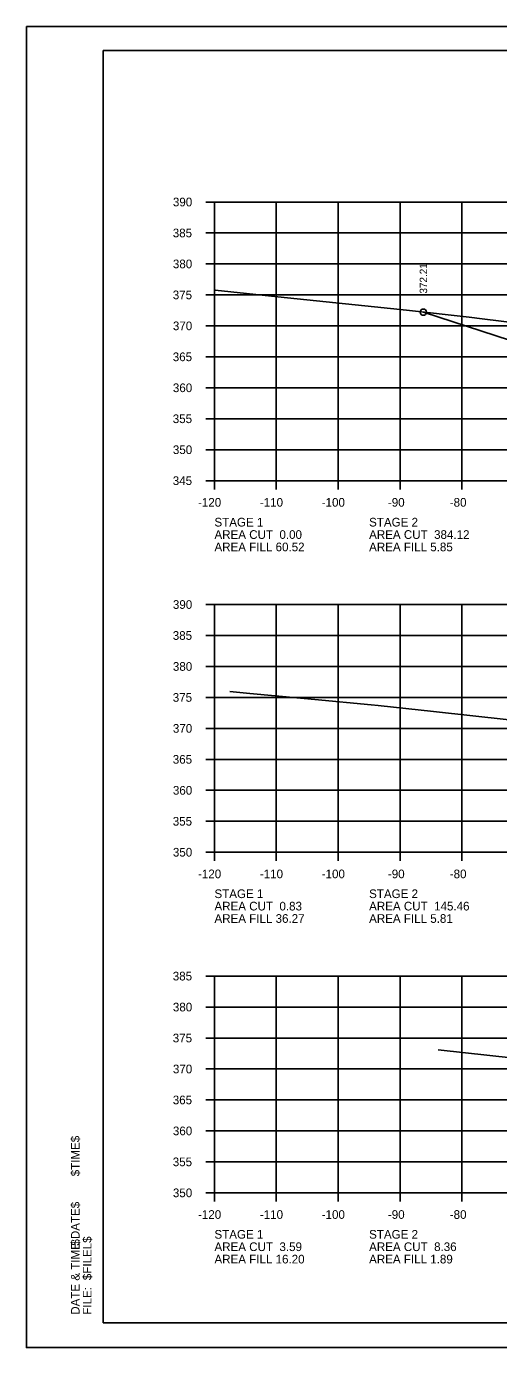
# Model space of a CAD drawing. Extents: x 1630712 to 1632516, y 782146 to 785403.
# Drawn here: x 1632182.6 to 1632258.9, y 783696.6 to 783910 of the extents above; entities that cross this region are included whole.
import ezdxf

# ---------------------------------------------------------------- set-up
doc = ezdxf.new("R2010")
doc.units = 0
for name, color, linetype in [('Default', 7, 'Continuous'), ('R_Axis', 7, 'Continuous'), ('R_Axis Annot', 7, 'Continuous'), ('R_Border', 7, 'Continuous'), ('R_Exist Surface', 7, 'Continuous'), ('R_Fin Surface', 7, 'Continuous'), ('R_Grid', 7, 'Continuous'), ('R_No Plot', 7, 'Continuous'), ('R_Xsect Elev', 7, 'Continuous')]:
    doc.layers.add(name, color=color, linetype=linetype)

msp = doc.modelspace()

# ---------------------------------------------------------------- linework, layer by layer
at = {"layer": 'R_Axis'}
for p, q in [((1632211.56, 783881.62), (1632212.96, 783881.62)), ((1632212.96, 783836.62), (1632212.96, 783881.62)), ((1632211.56, 783876.62), (1632212.96, 783876.62)), ((1632211.56, 783871.62), (1632212.96, 783871.62)), ((1632211.56, 783866.62), (1632212.96, 783866.62)), ((1632211.56, 783861.62), (1632212.96, 783861.62)), ((1632211.56, 783856.62), (1632212.96, 783856.62)), ((1632211.56, 783851.62), (1632212.96, 783851.62)), ((1632211.56, 783846.62), (1632212.96, 783846.62)), ((1632211.56, 783841.62), (1632212.96, 783841.62)), ((1632211.56, 783836.62), (1632212.96, 783836.62)), ((1632212.96, 783836.62), (1632492.96, 783836.62)), ((1632212.96, 783835.22), (1632212.96, 783836.62)), ((1632222.96, 783835.22), (1632222.96, 783836.62)), ((1632232.96, 783835.22), (1632232.96, 783836.62)), ((1632242.96, 783835.22), (1632242.96, 783836.62)), ((1632252.96, 783835.22), (1632252.96, 783836.62)), ((1632211.56, 783816.62), (1632212.96, 783816.62)), ((1632212.96, 783776.62), (1632212.96, 783816.62)), ((1632211.56, 783811.62), (1632212.96, 783811.62)), ((1632211.56, 783806.62), (1632212.96, 783806.62)), ((1632211.56, 783801.62), (1632212.96, 783801.62)), ((1632211.56, 783796.62), (1632212.96, 783796.62)), ((1632211.56, 783791.62), (1632212.96, 783791.62)), ((1632211.56, 783786.62), (1632212.96, 783786.62)), ((1632211.56, 783781.62), (1632212.96, 783781.62)), ((1632211.56, 783776.62), (1632212.96, 783776.62)), ((1632212.96, 783776.62), (1632492.96, 783776.62)), ((1632212.96, 783775.22), (1632212.96, 783776.62)), ((1632222.96, 783775.22), (1632222.96, 783776.62)), ((1632232.96, 783775.22), (1632232.96, 783776.62)), ((1632242.96, 783775.22), (1632242.96, 783776.62)), ((1632252.96, 783775.22), (1632252.96, 783776.62)), ((1632211.56, 783756.62), (1632212.96, 783756.62)), ((1632212.96, 783721.62), (1632212.96, 783756.62)), ((1632211.56, 783751.62), (1632212.96, 783751.62)), ((1632211.56, 783746.62), (1632212.96, 783746.62)), ((1632211.56, 783741.62), (1632212.96, 783741.62)), ((1632211.56, 783736.62), (1632212.96, 783736.62)), ((1632211.56, 783731.62), (1632212.96, 783731.62)), ((1632211.56, 783726.62), (1632212.96, 783726.62)), ((1632211.56, 783721.62), (1632212.96, 783721.62)), ((1632212.96, 783721.62), (1632492.96, 783721.62)), ((1632212.96, 783720.22), (1632212.96, 783721.62)), ((1632222.96, 783720.22), (1632222.96, 783721.62)), ((1632232.96, 783720.22), (1632232.96, 783721.62)), ((1632242.96, 783720.22), (1632242.96, 783721.62)), ((1632252.96, 783720.22), (1632252.96, 783721.62))]:
    msp.add_line(p, q, dxfattribs=at)
at = {"layer": 'R_Border'}
for p, q in [((1632194.96, 783906.08), (1632511.14, 783906.08)), ((1632194.96, 783700.62), (1632194.96, 783906.08)), ((1632511.14, 783700.62), (1632194.96, 783700.62))]:
    msp.add_line(p, q, dxfattribs=at)
at = {"layer": 'R_Exist Surface'}
for points in [[(1632212.96, 783867.43), (1632213.1, 783867.41), (1632223.18, 783866.31), (1632238.84, 783864.7), (1632243.99, 783864.13), (1632254.16, 783863.01), (1632256.26, 783862.76), (1632300.13, 783857.36)], [(1632215.45, 783802.57), (1632218.68, 783802.27), (1632226.86, 783801.5), (1632229.21, 783801.28), (1632238.28, 783800.41), (1632239.45, 783800.31), (1632248.39, 783799.37), (1632278.73, 783795.99)], [(1632249.13, 783744.72), (1632273.69, 783742.03), (1632298.1, 783739.36), (1632301.03, 783738.39), (1632313.8, 783733.93), (1632319.57, 783735.36), (1632321.19, 783735.74), (1632322.85, 783736.03), (1632323.29, 783736.12), (1632330.98, 783736.3), (1632332.54, 783736.34), (1632334.1, 783736.31), (1632342.1, 783736.17), (1632342.88, 783736.1), (1632345.78, 783735.86), (1632351.76, 783734.3), (1632353.45, 783733.85), (1632358.72, 783733.99), (1632375.15, 783734.43), (1632381.34, 783733.77), (1632385.36, 783733.3), (1632403.49, 783731.55)]]:
    msp.add_lwpolyline(points, dxfattribs=at)
at = {"layer": 'R_Fin Surface'}
msp.add_lwpolyline([(1632246.74, 783863.83), (1632281.81, 783852.44), (1632296.96, 783847.09), (1632310.79, 783850.54), (1632314.96, 783851.59), (1632320.96, 783851.83), (1632332.96, 783852.07), (1632344.96, 783851.83), (1632350.96, 783851.59), (1632355.14, 783850.54), (1632368.96, 783847.09), (1632368.96, 783847.09), (1632376.31, 783849.54)], dxfattribs=at)
at = {"layer": 'R_Grid'}
for p, q in [((1632212.96, 783881.62), (1632492.96, 783881.62)), ((1632212.96, 783836.62), (1632212.96, 783881.62)), ((1632222.96, 783836.62), (1632222.96, 783881.62)), ((1632232.96, 783836.62), (1632232.96, 783881.62)), ((1632242.96, 783836.62), (1632242.96, 783881.62)), ((1632252.96, 783836.62), (1632252.96, 783881.62)), ((1632212.96, 783876.62), (1632492.96, 783876.62)), ((1632212.96, 783871.62), (1632492.96, 783871.62)), ((1632212.96, 783866.62), (1632492.96, 783866.62)), ((1632212.96, 783861.62), (1632492.96, 783861.62)), ((1632212.96, 783856.62), (1632492.96, 783856.62)), ((1632212.96, 783851.62), (1632492.96, 783851.62)), ((1632212.96, 783846.62), (1632492.96, 783846.62)), ((1632212.96, 783841.62), (1632492.96, 783841.62)), ((1632212.96, 783836.62), (1632492.96, 783836.62)), ((1632212.96, 783816.62), (1632492.96, 783816.62)), ((1632212.96, 783776.62), (1632212.96, 783816.62)), ((1632222.96, 783776.62), (1632222.96, 783816.62)), ((1632232.96, 783776.62), (1632232.96, 783816.62)), ((1632242.96, 783776.62), (1632242.96, 783816.62)), ((1632252.96, 783776.62), (1632252.96, 783816.62)), ((1632212.96, 783811.62), (1632492.96, 783811.62)), ((1632212.96, 783806.62), (1632492.96, 783806.62)), ((1632212.96, 783801.62), (1632492.96, 783801.62)), ((1632212.96, 783796.62), (1632492.96, 783796.62)), ((1632212.96, 783791.62), (1632492.96, 783791.62)), ((1632212.96, 783786.62), (1632492.96, 783786.62)), ((1632212.96, 783781.62), (1632492.96, 783781.62)), ((1632212.96, 783776.62), (1632492.96, 783776.62)), ((1632212.96, 783756.62), (1632492.96, 783756.62)), ((1632212.96, 783721.62), (1632212.96, 783756.62)), ((1632222.96, 783721.62), (1632222.96, 783756.62)), ((1632232.96, 783721.62), (1632232.96, 783756.62)), ((1632242.96, 783721.62), (1632242.96, 783756.62)), ((1632252.96, 783721.62), (1632252.96, 783756.62)), ((1632212.96, 783751.62), (1632492.96, 783751.62)), ((1632212.96, 783746.62), (1632492.96, 783746.62)), ((1632212.96, 783741.62), (1632492.96, 783741.62)), ((1632212.96, 783736.62), (1632492.96, 783736.62)), ((1632212.96, 783731.62), (1632492.96, 783731.62)), ((1632212.96, 783726.62), (1632492.96, 783726.62)), ((1632212.96, 783721.62), (1632492.96, 783721.62))]:
    msp.add_line(p, q, dxfattribs=at)
at = {"layer": 'R_No Plot'}
for p, q in [((1632182.56, 783909.97), (1632515.9, 783909.97)), ((1632182.56, 783696.64), (1632515.9, 783696.64))]:
    msp.add_line(p, q, dxfattribs=at)
msp.add_lwpolyline([(1632182.56, 783909.97), (1632515.9, 783909.97), (1632515.9, 783696.63), (1632182.56, 783696.63)], close=True, dxfattribs=at)
msp.add_circle((1632246.74, 783863.83), 0.5, dxfattribs=at)

# ---------------------------------------------------------------- texts
at = {"layer": 'Default'}
for s, height, p in [('$TIME$', 1.397, (1632191.16, 783724.29)), ('$DATE$', 1.397, (1632191.16, 783713.11)), ('DATE & TIME:', 1.3968, (1632191.16, 783701.94)), ('$FILEL$', 1.397, (1632193.08, 783707.53)), ('FILE: ', 1.397, (1632193.08, 783701.94))]:
    msp.add_text(s, height=height, rotation=90, dxfattribs=at).set_placement(p)
at = {"layer": 'R_Axis'}
for p in [(1632212.96, 783836.62), (1632212.96, 783776.62), (1632212.96, 783721.62)]:
    msp.add_text('-', height=0.0001, dxfattribs=at).set_placement(p)
at = {"layer": 'R_Axis Annot'}
for s, p in [('390', (1632206.24, 783880.92)), ('385', (1632206.22, 783875.92)), ('380', (1632206.24, 783870.92)), ('375', (1632206.22, 783865.92)), ('370', (1632206.24, 783860.92)), ('365', (1632206.22, 783855.92)), ('360', (1632206.24, 783850.92)), ('355', (1632206.22, 783845.92)), ('350', (1632206.24, 783840.92)), ('345', (1632206.22, 783835.92)), ('-120', (1632210.3, 783832.42)), ('-110', (1632220.3, 783832.42)), ('-100', (1632230.3, 783832.42)), ('-90', (1632241, 783832.42)), ('-80', (1632251, 783832.42)), ('STAGE 1', (1632212.96, 783829.22)), ('STAGE 2', (1632237.96, 783829.22)), ('AREA CUT  0.00', (1632212.96, 783827.22)), ('AREA CUT  384.12', (1632237.96, 783827.22)), ('AREA FILL 60.52', (1632212.96, 783825.22)), ('AREA FILL 5.85', (1632237.96, 783825.22)), ('390', (1632206.24, 783815.92)), ('385', (1632206.22, 783810.92)), ('380', (1632206.24, 783805.92)), ('375', (1632206.22, 783800.92)), ('370', (1632206.24, 783795.92)), ('365', (1632206.22, 783790.92)), ('360', (1632206.24, 783785.92)), ('355', (1632206.22, 783780.92)), ('350', (1632206.24, 783775.92)), ('-120', (1632210.3, 783772.42)), ('-110', (1632220.3, 783772.42)), ('-100', (1632230.3, 783772.42)), ('-90', (1632241, 783772.42)), ('-80', (1632251, 783772.42)), ('STAGE 1', (1632212.96, 783769.22)), ('STAGE 2', (1632237.96, 783769.22)), ('AREA CUT  0.83', (1632212.96, 783767.22)), ('AREA CUT  145.46', (1632237.96, 783767.22)), ('AREA FILL 36.27', (1632212.96, 783765.22)), ('AREA FILL 5.81', (1632237.96, 783765.22)), ('385', (1632206.22, 783755.92)), ('380', (1632206.24, 783750.92)), ('375', (1632206.22, 783745.92)), ('370', (1632206.24, 783740.92)), ('365', (1632206.22, 783735.92)), ('360', (1632206.24, 783730.92)), ('355', (1632206.22, 783725.92)), ('350', (1632206.24, 783720.92)), ('-120', (1632210.3, 783717.42)), ('-110', (1632220.3, 783717.42)), ('-100', (1632230.3, 783717.42)), ('-90', (1632241, 783717.42)), ('-80', (1632251, 783717.42)), ('STAGE 1', (1632212.96, 783714.22)), ('STAGE 2', (1632237.96, 783714.22)), ('AREA CUT  3.59', (1632212.96, 783712.22)), ('AREA CUT  8.36', (1632237.96, 783712.22)), ('AREA FILL 16.20', (1632212.96, 783710.22)), ('AREA FILL 1.89', (1632237.96, 783710.22))]:
    msp.add_text(s, height=1.4, dxfattribs=at).set_placement(p)
at = {"layer": 'R_Xsect Elev'}
msp.add_text('372.21', height=1.2, rotation=90, dxfattribs=at).set_placement((1632247.34, 783866.83))

doc.saveas('drawing.dxf')
